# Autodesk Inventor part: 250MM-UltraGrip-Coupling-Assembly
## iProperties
Created: 2012-05
Part Number: 250MM-UltraGrip-Coupling-Assembly
Document SubType Name: Modeling
Designer: D Cole
Density: 1 g/cm^3
Author: D Cole
